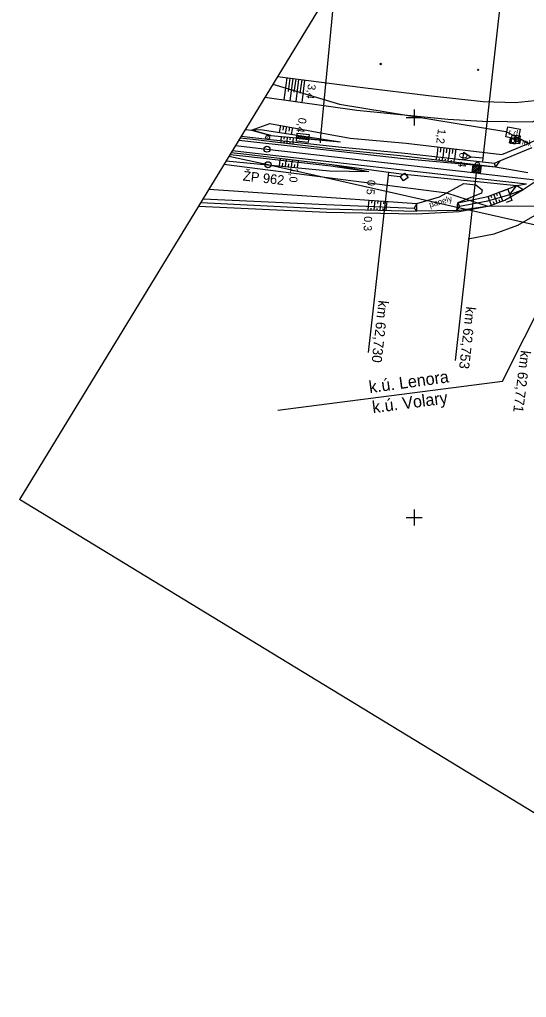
# Model space of a CAD drawing. Extents: x -804899 to -803847, y -1165742 to -1164942.
# Drawn here: x -804898.6 to -804772, y -1165320 to -1165075.5 of the extents above; entities that cross this region are included whole.
import ezdxf

# ---------------------------------------------------------------- set-up
doc = ezdxf.new("R2010")
doc.units = 0
for name, color, linetype in [('0381KM061-064P - Vrstva 1', 7, 'Continuous'), ('0381KM061-064P - Vrstva 16', 7, 'Continuous'), ('0381KM061-064P - Vrstva 23', 7, 'Continuous'), ('0381KM061-064P - Vrstva 27', 7, 'Continuous'), ('0381KM061-064P - Vrstva 3', 7, 'Continuous'), ('0381KM061-064P - Vrstva 33', 7, 'Continuous'), ('0381KM061-064P - Vrstva 4', 7, 'Continuous'), ('0381KM061-064P - Vrstva 43', 7, 'Continuous'), ('0381KM061-064P - Vrstva 48', 7, 'Continuous'), ('0381KM061-064P - Vrstva 49', 7, 'Continuous'), ('0381KM061-064P - Vrstva 51', 7, 'Continuous'), ('0381KM061-064P - Vrstva 55', 7, 'Continuous'), ('0381KM061-064P - Vrstva 7', 7, 'Continuous'), ('0381KM061-064P - Vrstva 8', 7, 'Continuous'), ('formát', 7, 'Continuous'), ('hran DP - hran DP', 7, 'Continuous'), ('krizky_1000 - Vrstva 1', 7, 'Continuous'), ('vyt_sit - polygon', 7, 'Continuous'), ('vyt_sit - stávající', 7, 'Continuous')]:
    doc.layers.add(name, color=color, linetype=linetype)

msp = doc.modelspace()

# ---------------------------------------------------------------- linework, layer by layer
at = {"layer": '0381KM061-064P - Vrstva 1'}
for points in [[(-804844.65, -1165107.07), (-804836.78, -1165107.96), (-804807.43, -1165111.28), (-804784.52, -1165113.87), (-804783.45, -1165113.99)], [(-804783.45, -1165113.99), (-804769.78, -1165115.58), (-804758.24, -1165117.11), (-804750.67, -1165118.27), (-804748.02, -1165118.72)]]:
    msp.add_lwpolyline(points, dxfattribs=at)
at = {"layer": '0381KM061-064P - Vrstva 16'}
for p, q in [((-804776.21, -1165106.34), (-804776.22, -1165106.34)), ((-804775.98, -1165105.22), (-804775.98, -1165105.22)), ((-804774.64, -1165105.59), (-804774.63, -1165105.59))]:
    msp.add_line(p, q, dxfattribs=at)
for points in [[(-804774.8, -1165106.64), (-804776.22, -1165106.34), (-804775.98, -1165105.22), (-804774.63, -1165105.59), (-804774.8, -1165106.64)], [(-804774.81, -1165106.64), (-804774.64, -1165105.59), (-804775.98, -1165105.22), (-804776.21, -1165106.34), (-804774.81, -1165106.64), (-804774.8, -1165106.64)], [(-804799.35, -1165123.41), (-804799.3, -1165121.51), (-804793.65, -1165119.83), (-804787.56, -1165116.52), (-804784.63, -1165116.88), (-804783.05, -1165118.1), (-804783.21, -1165118.97), (-804789.08, -1165121.4), (-804789.37, -1165123.31), (-804799.35, -1165123.41)]]:
    msp.add_lwpolyline(points, dxfattribs=at)
at = {"layer": '0381KM061-064P - Vrstva 23'}
msp.add_lwpolyline([(-804776.62, -1165102.34), (-804773.5, -1165102.91), (-804774.04, -1165105.5), (-804777.07, -1165104.85), (-804776.62, -1165102.34)], dxfattribs=at)
at = {"layer": '0381KM061-064P - Vrstva 27'}
for p, q in [((-804774.53, -1165105.54), (-804774.43, -1165105.56)), ((-804784.28, -1165111.73), (-804784.18, -1165111.73))]:
    msp.add_line(p, q, dxfattribs=at)
for centre in [(-804774.48, -1165105.55), (-804784.23, -1165111.73)]:
    msp.add_circle(centre, 0.5, dxfattribs=at)
at = {"layer": '0381KM061-064P - Vrstva 3'}
for p, q in [((-804784.52, -1165113.87), (-804789.79, -1165160.75)), ((-804783.3, -1165111.99), (-804785.51, -1165113.76)), ((-804783.83, -1165111.94), (-804785.45, -1165113.23)), ((-804784.36, -1165111.88), (-804785.4, -1165112.7)), ((-804784.88, -1165111.82), (-804785.34, -1165112.18)), ((-804783.36, -1165112.52), (-804784.99, -1165113.82)), ((-804783.42, -1165113.05), (-804784.46, -1165113.88)), ((-804783.48, -1165113.58), (-804783.93, -1165113.94))]:
    msp.add_line(p, q, dxfattribs=at)
msp.add_lwpolyline([(-804783.53, -1165113.98), (-804785.51, -1165113.76), (-804785.29, -1165111.77), (-804783.3, -1165111.99)], close=True, dxfattribs=at)
at = {"layer": '0381KM061-064P - Vrstva 33'}
for p, q in [((-804775.08, -1165104.96), (-804774.09, -1165105.07)), ((-804774.58, -1165105.01), (-804774.7, -1165106.01))]:
    msp.add_line(p, q, dxfattribs=at)
msp.add_lwpolyline([(-804775.52, -1165104.4), (-804773.53, -1165104.63), (-804773.76, -1165106.62), (-804775.75, -1165106.39), (-804775.52, -1165104.4)], dxfattribs=at)
at = {"layer": '0381KM061-064P - Vrstva 4'}
for points in [[(-804843.83, -1165105.73), (-804840.8, -1165106.06), (-804819.65, -1165108.38), (-804802.7, -1165110.3), (-804779.71, -1165112.39), (-804771.59, -1165113.78)], [(-804843.45, -1165105.1), (-804840.34, -1165105.46), (-804819.52, -1165107.92), (-804802.69, -1165109.64), (-804779.71, -1165112.39)], [(-804845.7, -1165108.79), (-804841.9, -1165109.22), (-804820.58, -1165111.74), (-804803.21, -1165114.08), (-804774.36, -1165117.01), (-804771.98, -1165116.64)], [(-804845.41, -1165108.32), (-804841.86, -1165108.69), (-804820.53, -1165111.13), (-804802.92, -1165113.13), (-804771.98, -1165116.64)]]:
    msp.add_lwpolyline(points, dxfattribs=at)
at = {"layer": '0381KM061-064P - Vrstva 43'}
msp.add_lwpolyline([(-804778.05, -1165118.46), (-804776.64, -1165117.94), (-804775.59, -1165120.75), (-804777, -1165121.27)], dxfattribs=at)
at = {"layer": '0381KM061-064P - Vrstva 48'}
for p, q in [((-804832.45, -1165095.65), (-804831.74, -1165090.13)), ((-804831.42, -1165093.54), (-804831, -1165090.23)), ((-804830.97, -1165095.86), (-804830.25, -1165090.32)), ((-804829.94, -1165093.74), (-804829.51, -1165090.42)), ((-804829.48, -1165096.06), (-804828.77, -1165090.52)), ((-804828.45, -1165093.95), (-804828.02, -1165090.61)), ((-804827.99, -1165096.27), (-804827.28, -1165090.71)), ((-804833.61, -1165103.81), (-804833.29, -1165102.02)), ((-804832.74, -1165103.22), (-804832.55, -1165102.15)), ((-804832.13, -1165104.04), (-804831.81, -1165102.29)), ((-804831.26, -1165103.46), (-804831.07, -1165102.42)), ((-804830.65, -1165104.27), (-804830.33, -1165102.56)), ((-804833.23, -1165105.8), (-804833.29, -1165106.29)), ((-804833.24, -1165105.79), (-804833.15, -1165104.77)), ((-804832.51, -1165106.08), (-804832.54, -1165106.38)), ((-804832.46, -1165105.46), (-804832.4, -1165104.84)), ((-804831.74, -1165105.96), (-804831.8, -1165106.47)), ((-804831.75, -1165105.96), (-804831.66, -1165104.91)), ((-804831.02, -1165106.25), (-804831.05, -1165106.55)), ((-804830.97, -1165105.61), (-804830.91, -1165104.98)), ((-804830.25, -1165106.12), (-804830.31, -1165106.64)), ((-804830.26, -1165106.12), (-804830.16, -1165105.05)), ((-804794.08, -1165107.35), (-804794.37, -1165109.84)), ((-804793.33, -1165107.44), (-804793.48, -1165108.68)), ((-804792.59, -1165107.53), (-804792.88, -1165110.01)), ((-804791.84, -1165107.62), (-804791.99, -1165108.86)), ((-804791.1, -1165107.71), (-804791.39, -1165110.18)), ((-804790.35, -1165107.79), (-804790.5, -1165109.03)), ((-804789.61, -1165107.88), (-804789.9, -1165110.35)), ((-804833.61, -1165112.12), (-804833.46, -1165110.65)), ((-804833.4, -1165110.23), (-804833.45, -1165110.65)), ((-804832.86, -1165112.2), (-804832.79, -1165111.47)), ((-804832.66, -1165110.31), (-804832.68, -1165110.53)), ((-804832.11, -1165112.27), (-804831.97, -1165110.82)), ((-804831.91, -1165110.4), (-804831.96, -1165110.82)), ((-804831.17, -1165110.49), (-804831.19, -1165110.7)), ((-804830.62, -1165112.41), (-804830.48, -1165111)), ((-804830.42, -1165110.58), (-804830.47, -1165111)), ((-804829.68, -1165110.67), (-804829.7, -1165110.87)), ((-804829.13, -1165112.56), (-804828.99, -1165111.17)), ((-804828.93, -1165110.75), (-804828.98, -1165111.17)), ((-804794.47, -1165110.62), (-804794.37, -1165109.84)), ((-804793.72, -1165110.71), (-804793.67, -1165110.32)), ((-804792.98, -1165110.8), (-804792.88, -1165110.01)), ((-804792.23, -1165110.89), (-804792.18, -1165110.49)), ((-804791.49, -1165110.98), (-804791.39, -1165110.18)), ((-804790.74, -1165111.07), (-804790.69, -1165110.67)), ((-804790, -1165111.16), (-804789.9, -1165110.35)), ((-804831.37, -1165112.34), (-804831.3, -1165111.62)), ((-804829.87, -1165112.48), (-804829.81, -1165111.78)), ((-804779.17, -1165119.64), (-804779.44, -1165118.91)), ((-804778.26, -1165119.92), (-804778.74, -1165118.65)), ((-804811.36, -1165120.67), (-804811.46, -1165122.21)), ((-804810.61, -1165120.72), (-804810.66, -1165121.48)), ((-804809.86, -1165120.78), (-804809.96, -1165122.27)), ((-804809.11, -1165120.83), (-804809.16, -1165121.56)), ((-804808.36, -1165120.88), (-804808.46, -1165122.33)), ((-804807.62, -1165120.93), (-804807.67, -1165121.65)), ((-804806.87, -1165120.98), (-804806.97, -1165122.39)), ((-804781.15, -1165120.77), (-804781.55, -1165119.71)), ((-804781.16, -1165120.78), (-804780.73, -1165121.92)), ((-804780.59, -1165120.11), (-804780.84, -1165119.44)), ((-804780.27, -1165121), (-804780.03, -1165121.66)), ((-804779.71, -1165120.34), (-804780.14, -1165119.18)), ((-804779.71, -1165120.35), (-804779.33, -1165121.4)), ((-804778.85, -1165120.54), (-804778.62, -1165121.14)), ((-804778.28, -1165119.92), (-804777.92, -1165120.88)), ((-804811.47, -1165123.14), (-804811.45, -1165122.21)), ((-804810.72, -1165123.15), (-804810.71, -1165122.7)), ((-804809.97, -1165123.17), (-804809.95, -1165122.27)), ((-804809.22, -1165123.19), (-804809.21, -1165122.74)), ((-804808.47, -1165123.2), (-804808.45, -1165122.33)), ((-804807.72, -1165123.22), (-804807.71, -1165122.79)), ((-804806.97, -1165123.24), (-804806.95, -1165122.39))]:
    msp.add_line(p, q, dxfattribs=at)
at = {"layer": '0381KM061-064P - Vrstva 49'}
for p, q in [((-804808.18, -1165086.83), (-804808.54, -1165086.48)), ((-804808.18, -1165086.48), (-804808.54, -1165086.83)), ((-804783.82, -1165088.3), (-804784.18, -1165087.95)), ((-804783.82, -1165087.95), (-804784.18, -1165088.3))]:
    msp.add_line(p, q, dxfattribs=at)
for points in [[(-804782.93, -1165100.95), (-804770.45, -1165101.13), (-804760.77, -1165096.17), (-804750.38, -1165086.38), (-804747.77, -1165080.29)], [(-804834.14, -1165089.82), (-804812.85, -1165092.56), (-804796.39, -1165094.52), (-804782.73, -1165096.03), (-804774.67, -1165096.28), (-804769.92, -1165095.77)], [(-804837.28, -1165094.97), (-804814.35, -1165098.18)], [(-804778.12, -1165109.25), (-804771.87, -1165106.67), (-804764.3, -1165103.24), (-804757.01, -1165099.37), (-804754.14, -1165096.35)], [(-804814.35, -1165098.18), (-804791.62, -1165100.43), (-804782.93, -1165100.95)], [(-804840.64, -1165103.22), (-804836.05, -1165101.51), (-804816.03, -1165105.18), (-804802.02, -1165106.41), (-804778.12, -1165109.25)], [(-804842.2, -1165103.05), (-804840.64, -1165103.22)], [(-804840.64, -1165103.22), (-804838.47, -1165103.07), (-804818.4, -1165106.14)], [(-804840.64, -1165103.22), (-804835.82, -1165104.53), (-804840.64, -1165103.22), (-804835.82, -1165104.53), (-804818.4, -1165106.14)], [(-804843.45, -1165105.1), (-804840.34, -1165105.46), (-804819.52, -1165107.92), (-804802.69, -1165109.64), (-804779.71, -1165112.39)], [(-804843.18, -1165104.66), (-804835.93, -1165105.5), (-804818.93, -1165107.36), (-804802.32, -1165108.93), (-804779.97, -1165111.49)], [(-804845.7, -1165108.79), (-804841.9, -1165109.22), (-804820.58, -1165111.74), (-804811.31, -1165113.56)], [(-804778.59, -1165110.84), (-804770.54, -1165107.5)], [(-804846.95, -1165110.84), (-804821.13, -1165113.33), (-804811.31, -1165113.56)], [(-804845.98, -1165109.25), (-804842.05, -1165109.66), (-804820.85, -1165112.11), (-804811.31, -1165113.56)], [(-804779.71, -1165112.39), (-804779.97, -1165111.49), (-804778.59, -1165110.84)], [(-804778.59, -1165110.84), (-804779.71, -1165112.39)], [(-804851.29, -1165117.97), (-804821.94, -1165119.94), (-804799.3, -1165121.51)], [(-804789.08, -1165121.4), (-804781.63, -1165119.74), (-804774.36, -1165117.01)], [(-804781.18, -1165122.08), (-804777.38, -1165120.68), (-804772.77, -1165118.03)], [(-804776.1, -1165119.27), (-804774.36, -1165117.01)], [(-804776.1, -1165119.27), (-804772.77, -1165118.03)], [(-804774.36, -1165117.01), (-804772.77, -1165118.03)], [(-804853.31, -1165121.27), (-804821.85, -1165122.9), (-804799.35, -1165123.41)], [(-804852.74, -1165120.35), (-804821.99, -1165121.8), (-804800.02, -1165122.66)], [(-804788.67, -1165122.22), (-804781.58, -1165120.9), (-804776.1, -1165119.27)], [(-804799.3, -1165121.51), (-804800.02, -1165122.66), (-804799.35, -1165123.41)], [(-804789.37, -1165123.31), (-804789.08, -1165121.4)], [(-804789.08, -1165121.4), (-804788.67, -1165122.22), (-804789.37, -1165123.31)], [(-804789.37, -1165123.31), (-804781.18, -1165122.08)]]:
    msp.add_lwpolyline(points, dxfattribs=at)
at = {"layer": '0381KM061-064P - Vrstva 51'}
for points in [[(-804799.4, -1165124.13), (-804788.79, -1165123.56), (-804781.18, -1165122.08), (-804777.38, -1165120.68), (-804772.77, -1165118.03), (-804766.25, -1165113.72), (-804759.19, -1165108.08), (-804752.39, -1165104.15), (-804745.74, -1165101.09), (-804737.37, -1165099.16), (-804728.56, -1165098.53)], [(-804786.51, -1165130.38), (-804780.05, -1165129.08), (-804774.13, -1165126.91), (-804767.62, -1165123.23), (-804757.45, -1165115.32), (-804754.9, -1165113.7), (-804749.49, -1165110.74), (-804743.99, -1165108.46), (-804736.29, -1165106.6), (-804728.9, -1165105.9)], [(-804853.87, -1165122.19), (-804821.92, -1165123.67), (-804799.4, -1165124.13)]]:
    msp.add_lwpolyline(points, dxfattribs=at)
at = {"layer": '0381KM061-064P - Vrstva 55'}
msp.add_lwpolyline([(-804834.02, -1165173.21), (-804777.95, -1165165.95), (-804761.65, -1165133.49), (-804755.48, -1165121.19), (-804751.26, -1165114.04), (-804741.92, -1165100.8), (-804736.13, -1165096.49), (-804701.79, -1165069.72), (-804628.3, -1165012.44)], dxfattribs=at)
at = {"layer": '0381KM061-064P - Vrstva 7'}
msp.add_line((-804836.67, -1165105.01), (-804836.57, -1165105.03), dxfattribs=at)
for centre, radius in [((-804836.62, -1165105.02), 0.5), ((-804836.78, -1165107.96), 0.75)]:
    msp.add_circle(centre, radius, dxfattribs=at)
at = {"layer": '0381KM061-064P - Vrstva 8'}
for p, q in [((-804782.75, -1165110.24), (-804774.89, -1165040.2)), ((-804823.36, -1165105.59), (-804819.58, -1165065.95)), ((-804829.06, -1165104.6), (-804829.31, -1165104.79)), ((-804828.53, -1165104.66), (-804829.3, -1165105.27)), ((-804828.01, -1165104.72), (-804828.78, -1165105.33)), ((-804827.48, -1165104.77), (-804828.25, -1165105.39)), ((-804826.95, -1165104.83), (-804827.72, -1165105.45)), ((-804826.42, -1165104.89), (-804827.2, -1165105.51)), ((-804826.35, -1165105.31), (-804826.67, -1165105.57)), ((-804823.44, -1165106.34), (-804823.28, -1165104.85)), ((-804787.62, -1165108.74), (-804785.73, -1165109.94)), ((-804782.82, -1165110.99), (-804782.67, -1165109.49)), ((-804806.43, -1165113.71), (-804806.59, -1165115.21)), ((-804806.51, -1165114.46), (-804811.49, -1165158.76))]:
    msp.add_line(p, q, dxfattribs=at)
for points in [[(-804826.45, -1165106.25), (-804829.43, -1165105.91), (-804829.21, -1165103.92), (-804826.23, -1165104.26), (-804826.45, -1165106.25)], [(-804826.34, -1165105.26), (-804823.36, -1165105.59)], [(-804782.75, -1165110.24), (-804785.73, -1165109.94), (-804787.82, -1165110.73), (-804787.62, -1165108.74), (-804785.73, -1165109.94)], [(-804806.51, -1165114.46), (-804803.53, -1165114.8), (-804802.42, -1165113.91), (-804801.54, -1165115.02), (-804802.65, -1165115.9), (-804803.53, -1165114.8)]]:
    msp.add_lwpolyline(points, dxfattribs=at)
msp.add_lwpolyline([(-804826.38, -1165105.6), (-804829.36, -1165105.26), (-804829.28, -1165104.57), (-804826.3, -1165104.91)], close=True, dxfattribs=at)
at = {"layer": 'formát'}
for p in [(-804743.98, -1164941.92), (-804360.64, -1165523.44)]:
    msp.add_line(p, (-804898.57, -1165195.52), dxfattribs=at)
at = {"layer": 'hran DP - hran DP'}
for p, q in [((-804835.27, -1165091.67), (-804818.68, -1165096.66)), ((-804818.68, -1165096.66), (-804777.08, -1165103.56)), ((-804777.08, -1165103.56), (-804771.09, -1165106.6)), ((-804791.88, -1165118.97), (-804847.53, -1165111.8)), ((-804781.51, -1165122.32), (-804791.88, -1165118.97)), ((-804765.27, -1165122.22), (-804781.51, -1165122.32))]:
    msp.add_line(p, q, dxfattribs=at)
at = {"layer": 'krizky_1000 - Vrstva 1'}
for points in [[(-804800, -1165098), (-804800, -1165102)], [(-804802, -1165100), (-804798, -1165100)], [(-804800, -1165198), (-804800, -1165202)], [(-804802, -1165200), (-804798, -1165200)]]:
    msp.add_lwpolyline(points, dxfattribs=at)
at = {"layer": 'vyt_sit - polygon'}
for p, q in [((-804836.52, -1165111.83), (-804846.32, -1165109.81)), ((-804641.93, -1165155.93), (-804836.52, -1165111.83))]:
    msp.add_line(p, q, dxfattribs=at)
at = {"layer": 'vyt_sit - stávající'}
msp.add_line((-804836.57, -1165111.8), (-804836.48, -1165111.85), dxfattribs=at)
msp.add_circle((-804836.52, -1165111.83), 0.756, dxfattribs=at)

# ---------------------------------------------------------------- texts
at = {"layer": '0381KM061-064P - Vrstva 16'}
for s, rotation, p in [('panel.', 348.0707, (-804776, -1165106.18)), ('panely', 16.5596, (-804796.03, -1165122.6))]:
    msp.add_text(s, height=1.5, rotation=rotation, dxfattribs=at).set_placement(p)
at = {"layer": '0381KM061-064P - Vrstva 23'}
msp.add_text('r.d.', height=1.5, rotation=349.7146, dxfattribs=at).set_placement((-804776.52, -1165104.36))
at = {"layer": '0381KM061-064P - Vrstva 3'}
msp.add_text('km 62,753', height=2.5, rotation=263.5832, dxfattribs=at).set_placement((-804787.04, -1165147.22))
at = {"layer": '0381KM061-064P - Vrstva 4'}
msp.add_text('km 62,771', height=2.5, rotation=262.8793, dxfattribs=at).set_placement((-804773.35, -1165158.16))
at = {"layer": '0381KM061-064P - Vrstva 48'}
for s, rotation, p in [('3,4', 262.6656, (-804826.51, -1165091.58)), ('0,4', 259.6289, (-804828.81, -1165099.95)), ('1,2', 263.2123, (-804794.05, -1165102.78)), ('0,4', 263.1664, (-804788.64, -1165108.7)), ('1,0', 264.4873, (-804830.87, -1165112.47)), ('0,5', 266.024, (-804811.67, -1165115.58)), ('0,3', 268.6994, (-804812.52, -1165124.7))]:
    msp.add_text(s, height=2, rotation=rotation, dxfattribs=at).set_placement(p)
at = {"layer": '0381KM061-064P - Vrstva 55'}
for s, rotation, p in [('k.ú. Lenora', 7.7713, (-804811.1, -1165168.94)), ('k.ú. Volary', 7.4655, (-804810.29, -1165173.96))]:
    msp.add_text(s, height=3, rotation=rotation, dxfattribs=at).set_placement(p)
at = {"layer": '0381KM061-064P - Vrstva 8'}
msp.add_text('km 62,730', height=2.5, rotation=263.5832, dxfattribs=at).set_placement((-804808.89, -1165145.66))
at = {"layer": 'vyt_sit - stávající'}
msp.add_text('ŽP 962', height=2.4, rotation=353.5611, dxfattribs=at).set_placement((-804842.86, -1165115.77))

doc.saveas('drawing.dxf')
